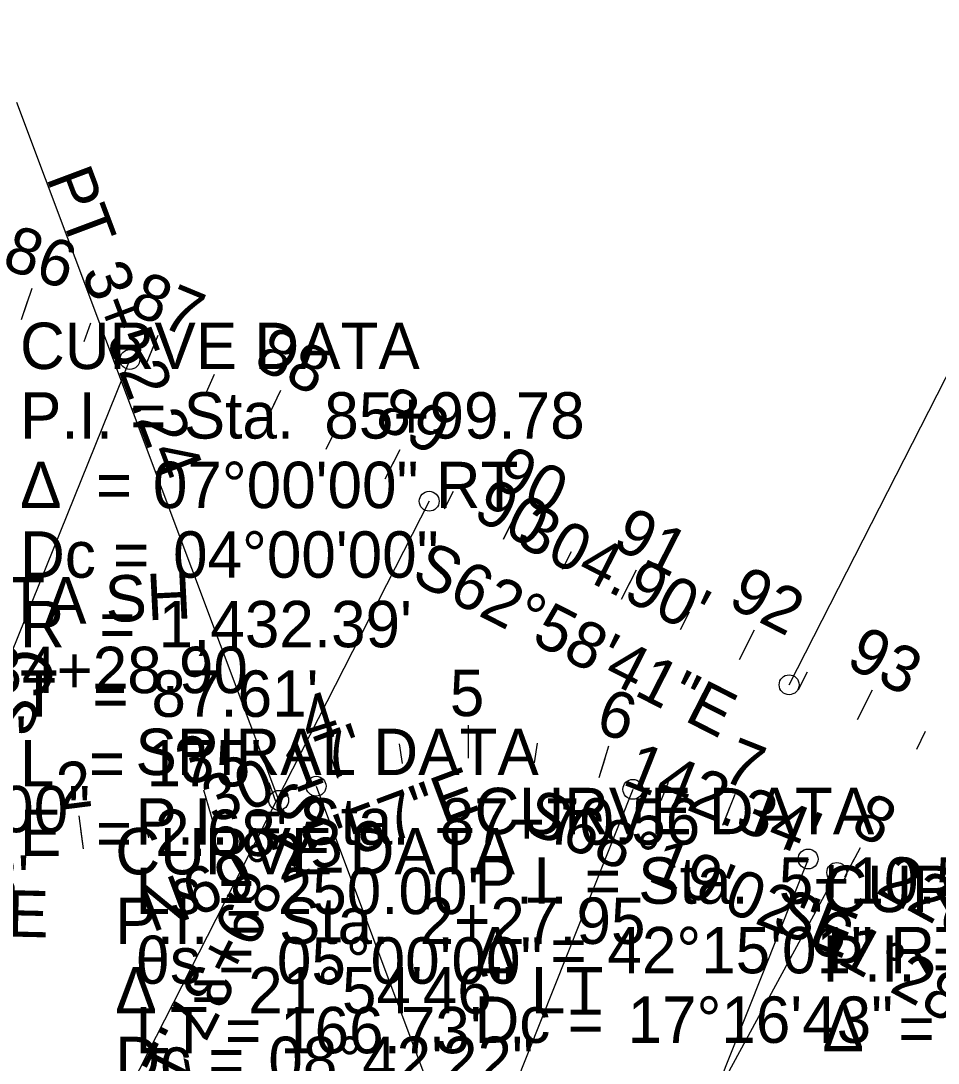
# Model space of a CAD drawing. Extents: x 2000474 to 2003418, y 251807 to 253801.
# Drawn here: x 2001296 to 2001988, y 252692 to 253479 of the extents above; entities that cross this region are included whole.
import ezdxf

# ---------------------------------------------------------------- set-up
doc = ezdxf.new("R2010")
doc.units = 0
for name, color, linetype in [('BD_X_Building', 7, 'Continuous'), ('DR_X_Flow_Arrow', 7, 'Continuous'), ('DV_X_Lot_Line', 7, 'Continuous'), ('DV_X_Property_Line', 7, 'Continuous'), ('DV_X_Township_Line', 7, 'Continuous'), ('GE_P_Alignment_100_Stations', 7, 'Continuous'), ('RW_P_Text', 7, 'Continuous'), ('RW_X_CL_100_Stations', 7, 'Continuous'), ('RW_X_CL_500_Stations', 7, 'Continuous'), ('SC_Scratch1', 7, 'Continuous'), ('SC_Scratch3', 7, 'Continuous'), ('SC_Scratch5', 7, 'Continuous'), ('SC_Shading1', 7, 'Continuous'), ('TX_X_50', 7, 'Continuous')]:
    doc.layers.add(name, color=color, linetype=linetype)

msp = doc.modelspace()

# ---------------------------------------------------------------- linework, layer by layer
at = {"layer": 'DR_X_Flow_Arrow'}
for p, q in [((2001490.69, 252890.46), (2001293.08, 253417.11)), ((2001633.98, 252922.2), (2001633.88, 252947.2)), ((2001535.56, 252906.8), (2001528.03, 252930.64)), ((2001584.19, 252918.22), (2001581.87, 252933.04)), ((2001683.81, 252918.65), (2001686, 252933.49)), ((2001732.54, 252907.66), (2001739.86, 252931.57)), ((2001488.59, 252889.68), (2001483.37, 252903.74)), ((2001779.38, 252890.21), (2001784.92, 252904.15)), ((2001441.1, 252874.07), (2001434.2, 252898.1)), ((2001518.94, 252901.06), (2001716.55, 252374.42)), ((2001757.95, 252898.74), (2001550.12, 252376.04)), ((2001825.84, 252871.74), (2001835.08, 252894.97)), ((2001343.26, 252853.87), (2001340.08, 252878.67)), ((2001392.56, 252862.11), (2001389.53, 252876.8)), ((2001872.3, 252853.27), (2001877.84, 252867.21)), ((2001917.84, 252832.75), (2001929.78, 252854.72)), ((2001890.21, 252846.15), (2001682.39, 252323.45)), ((2001911.83, 252836.02), (2001643.21, 252341.8)), ((2001961.77, 252808.88), (2001968.93, 252822.05))]:
    msp.add_line(p, q, dxfattribs=at)
for centre in [(2001518.94, 252901.06), (2001757.95, 252898.74), (2001490.69, 252890.46), (2001890.21, 252846.15), (2001911.83, 252836.02)]:
    msp.add_circle(centre, 7.5, dxfattribs=at)
at = {"layer": 'DV_X_Lot_Line'}
for p, q in [((2001633.98, 252922.2), (2001633.88, 252947.2)), ((2001535.56, 252906.8), (2001531.04, 252921.11)), ((2001732.54, 252907.66), (2001736.93, 252922)), ((2001441.1, 252874.07), (2001436.96, 252888.49)), ((2001825.84, 252871.74), (2001831.38, 252885.68)), ((2001343.26, 252853.87), (2001341.35, 252868.75)), ((2001917.84, 252832.75), (2001925, 252845.93))]:
    msp.add_line(p, q, dxfattribs=at)
at = {"layer": 'DV_X_Property_Line'}
for p, q in [((2001296.64, 253253.38), (2001301.41, 253267.6)), ((2001390.27, 253218.31), (2001396.01, 253232.17)), ((2001481.5, 253177.4), (2001487.96, 253190.94)), ((2001571.11, 253133.02), (2001577.9, 253146.4)), ((2001660.21, 253087.61), (2001666.93, 253100.79)), ((2001749.29, 253042.17), (2001756.11, 253055.54)), ((2001838.37, 252996.74), (2001845.19, 253010.1)), ((2001927.5, 252951.39), (2001934.25, 252964.78))]:
    msp.add_line(p, q, dxfattribs=at)
at = {"layer": 'RW_P_Text'}
for p, q in [((2001490.69, 252890.46), (2001293.08, 253417.11)), ((2001633.98, 252922.2), (2001633.92, 252937.2)), ((2001518.94, 252901.06), (2001716.55, 252374.42)), ((2001757.95, 252898.74), (2001550.12, 252376.04)), ((2001890.21, 252846.15), (2001682.39, 252323.45)), ((2001911.83, 252836.02), (2001643.21, 252341.8))]:
    msp.add_line(p, q, dxfattribs=at)
for centre in [(2001518.94, 252901.06), (2001757.95, 252898.74), (2001490.69, 252890.46), (2001890.21, 252846.15), (2001911.83, 252836.02)]:
    msp.add_circle(centre, 7.5, dxfattribs=at)
at = {"layer": 'RW_X_CL_100_Stations'}
for p, q in [((2001875.85, 252977.63), (2002131.41, 253478.72)), ((2001490.69, 252890.46), (2001293.08, 253417.11)), ((2001378.39, 253223.18), (2001167.48, 252701.72)), ((2001604.23, 253116.16), (2001348.67, 252615.06)), ((2001518.94, 252901.06), (2001716.55, 252374.42)), ((2001757.95, 252898.74), (2001550.12, 252376.04)), ((2001890.21, 252846.15), (2001682.39, 252323.45)), ((2001911.83, 252836.02), (2001643.21, 252341.8))]:
    msp.add_line(p, q, dxfattribs=at)
for centre in [(2001378.39, 253223.18), (2001604.23, 253116.16), (2001875.85, 252977.63), (2001518.94, 252901.06), (2001757.95, 252898.74), (2001490.69, 252890.46), (2001890.21, 252846.15), (2001911.83, 252836.02)]:
    msp.add_circle(centre, 7.5, dxfattribs=at)
at = {"layer": 'SC_Scratch3'}
for p, q in [((2001875.85, 252977.63), (2002131.41, 253478.72)), ((2001378.39, 253223.18), (2001167.48, 252701.72)), ((2001604.23, 253116.16), (2001348.67, 252615.06)), ((2001660.21, 253087.61), (2001671.57, 253109.88))]:
    msp.add_line(p, q, dxfattribs=at)
for centre in [(2001378.39, 253223.18), (2001604.23, 253116.16), (2001875.85, 252977.63)]:
    msp.add_circle(centre, 7.5, dxfattribs=at)
at = {"layer": 'TX_X_50'}
for p, q in [((2001875.85, 252977.63), (2002131.41, 253478.72)), ((2001296.64, 253253.38), (2001304.59, 253277.09)), ((2001343.76, 253236.66), (2001349.02, 253250.71)), ((2001390.27, 253218.31), (2001399.84, 253241.41)), ((2001378.39, 253223.18), (2001167.48, 252701.72)), ((2001436.15, 253198.45), (2001442.31, 253212.13)), ((2001481.5, 253177.4), (2001492.27, 253199.96)), ((2001526.44, 253155.48), (2001533.12, 253168.92)), ((2001571.11, 253133.02), (2001582.43, 253155.31)), ((2001615.67, 253110.32), (2001622.48, 253123.69)), ((2001604.23, 253116.16), (2001348.67, 252615.06)), ((2001660.21, 253087.61), (2001671.57, 253109.88)), ((2001704.75, 253064.89), (2001711.56, 253078.25)), ((2001749.29, 253042.17), (2001760.65, 253064.45)), ((2001793.83, 253019.46), (2001800.65, 253032.82)), ((2001838.37, 252996.74), (2001849.73, 253019.01)), ((2001882.92, 252974.03), (2001889.73, 252987.39)), ((2001927.5, 252951.39), (2001938.75, 252973.71)), ((2001972.26, 252929.11), (2001978.86, 252942.59))]:
    msp.add_line(p, q, dxfattribs=at)
for centre in [(2001378.39, 253223.18), (2001604.23, 253116.16), (2001875.85, 252977.63)]:
    msp.add_circle(centre, 7.5, dxfattribs=at)

# ---------------------------------------------------------------- texts
at = {"layer": 'BD_X_Building'}
for s, rotation, p in [("30.17'", 20.5675, (2001441.43, 252872.61)), ("142.34'", 338.31729, (2001748.96, 252902.94)), ('N69°25\'57"E', 20.5675, (2001395.04, 252790.49)), ('S68°19\'02"E', 338.31729, (2001673.29, 252867.83)), ("226.12'", 331.47468, (2001940.21, 252821.26)), ('S88°39\'17"E', 358.65462, (2001053.99, 252793.14)), ('S61°28\'29"E', 331.47468, (2001860.9, 252795.41))]:
    msp.add_text(s, height=35, rotation=rotation, dxfattribs=at).set_placement(p)
for s, p in [('CURVE DATA', (2001638.44, 252864.9)), ('CURVE DATA', (2001367.36, 252834.58)), ('P.I. = Sta. ', (2001638.44, 252812.4)), ('5+10.53', (2001868.05, 252812.4)), ('CURVE DATA', (2001901.02, 252806.08)), ('P.I. = Sta. ', (2001367.36, 252782.08)), ('2+27.95', (2001596.97, 252782.08)), ('Δ  = ', (2001638.44, 252759.9)), ('42°15\'01" RT', (2001738.72, 252759.9)), ('P.I. = Sta. ', (2001901.02, 252753.58)), ('Δ  = ', (2001367.36, 252729.58)), ('21°54\'46" LT', (2001467.64, 252729.58)), ('Dc = ', (2001638.44, 252707.4)), ('17°16\'43"', (2001753.93, 252707.4)), ('Δ  = ', (2001901.02, 252701.08)), ('Dc = ', (2001367.36, 252677.08)), ('08°42\'22"', (2001482.85, 252677.08))]:
    msp.add_text(s, height=35, dxfattribs=at).set_placement(p)
at = {"layer": 'DR_X_Flow_Arrow'}
for s, rotation, p in [('PT', 290.5675, (2001314.96, 253360.46)), ('3+52.24', 290.5675, (2001341.69, 253289.22)), ('5', 0.24994, (2001619.85, 252953.97)), ('4', 17.52864, (2001513.47, 252932.6)), ('6', 342.97124, (2001728.6, 252942.16)), ('3', 16.01907, (2001419.23, 252900.91)), ('7', 338.31729, (2001823.86, 252906.16)), ('2', 7.31304, (2001325.66, 252883.12)), ('8', 331.47468, (2001920.92, 252867.31))]:
    msp.add_text(s, height=35, rotation=rotation, dxfattribs=at).set_placement(p)
at = {"layer": 'DV_X_Lot_Line'}
msp.add_text('5', height=35, rotation=0.24994, dxfattribs=at).set_placement((2001619.85, 252953.97))
at = {"layer": 'DV_X_Property_Line'}
msp.add_text('90', height=35, rotation=332.97809, dxfattribs=at).set_placement((2001636.01, 253103.81))
at = {"layer": 'DV_X_Township_Line'}
for s, rotation, p in [("30.17'", 20.5675, (2001441.43, 252872.61)), ("142.34'", 338.31729, (2001748.96, 252902.94)), ('N69°25\'57"E', 20.5675, (2001395.04, 252790.49)), ('S68°19\'02"E', 338.31729, (2001673.29, 252867.83)), ("226.12'", 331.47468, (2001940.21, 252821.26)), ('S88°39\'17"E', 358.65462, (2001053.99, 252793.14)), ('S61°28\'29"E', 331.47468, (2001860.9, 252795.41))]:
    msp.add_text(s, height=35, rotation=rotation, dxfattribs=at).set_placement(p)
for s, p in [('CURVE DATA', (2001638.44, 252864.9)), ('CURVE DATA', (2001367.36, 252834.58)), ('P.I. = Sta. ', (2001638.44, 252812.4)), ('5+10.53', (2001868.05, 252812.4)), ('CURVE DATA', (2001901.02, 252806.08)), ('P.I. = Sta. ', (2001367.36, 252782.08)), ('2+27.95', (2001596.97, 252782.08)), ('Δ  = ', (2001638.44, 252759.9)), ('42°15\'01" RT', (2001738.72, 252759.9)), ('P.I. = Sta. ', (2001901.02, 252753.58)), ('Δ  = ', (2001367.36, 252729.58)), ('21°54\'46" LT', (2001467.64, 252729.58)), ('Dc = ', (2001638.44, 252707.4)), ('17°16\'43"', (2001753.93, 252707.4)), ('Δ  = ', (2001901.02, 252701.08)), ('Dc = ', (2001367.36, 252677.08)), ('08°42\'22"', (2001482.85, 252677.08))]:
    msp.add_text(s, height=35, dxfattribs=at).set_placement(p)
at = {"layer": 'GE_P_Alignment_100_Stations'}
for s, rotation, p in [("30.17'", 20.5675, (2001441.43, 252872.61)), ("142.34'", 338.31729, (2001748.96, 252902.94)), ('N69°25\'57"E', 20.5675, (2001395.04, 252790.49)), ('S68°19\'02"E', 338.31729, (2001673.29, 252867.83)), ("226.12'", 331.47468, (2001940.21, 252821.26)), ('S88°39\'17"E', 358.65462, (2001053.99, 252793.14)), ('S61°28\'29"E', 331.47468, (2001860.9, 252795.41))]:
    msp.add_text(s, height=35, rotation=rotation, dxfattribs=at).set_placement(p)
for s, p in [('CURVE DATA', (2001638.44, 252864.9)), ('CURVE DATA', (2001367.36, 252834.58)), ('P.I. = Sta. ', (2001638.44, 252812.4)), ('5+10.53', (2001868.05, 252812.4)), ('CURVE DATA', (2001901.02, 252806.08)), ('P.I. = Sta. ', (2001367.36, 252782.08)), ('2+27.95', (2001596.97, 252782.08)), ('Δ  = ', (2001638.44, 252759.9)), ('42°15\'01" RT', (2001738.72, 252759.9)), ('P.I. = Sta. ', (2001901.02, 252753.58)), ('Δ  = ', (2001367.36, 252729.58)), ('21°54\'46" LT', (2001467.64, 252729.58)), ('Dc = ', (2001638.44, 252707.4)), ('17°16\'43"', (2001753.93, 252707.4)), ('Δ  = ', (2001901.02, 252701.08)), ('Dc = ', (2001367.36, 252677.08)), ('08°42\'22"', (2001482.85, 252677.08))]:
    msp.add_text(s, height=35, dxfattribs=at).set_placement(p)
at = {"layer": 'RW_P_Text'}
for s, p in [('PT', (2001314.96, 253360.46)), ('3+52.24', (2001341.69, 253289.22))]:
    msp.add_text(s, height=35, rotation=290.5675, dxfattribs=at).set_placement(p)
at = {"layer": 'RW_X_CL_100_Stations'}
for s, rotation, p in [('PT', 290.5675, (2001314.96, 253360.46)), ('3+52.24', 290.5675, (2001341.69, 253289.22)), ("304.90'", 332.97809, (2001668.09, 253084.25)), ('S62°58\'41"E', 332.97809, (2001589.48, 253056.33)), ('CS', 247.97811, (2001292.45, 253009.12)), ('ST', 242.97809, (2001498.72, 252907.98)), ('89+37.17', 242.97809, (2001464.15, 252840.2))]:
    msp.add_text(s, height=35, rotation=rotation, dxfattribs=at).set_placement(p)
at = {"layer": 'RW_X_CL_500_Stations'}
for s, p in [('CURVE DATA', (2001295.48, 253215.96)), ('P.I. = Sta. ', (2001295.48, 253163.46)), ('85+99.78', (2001525.08, 253163.46)), ('Δ  = ', (2001295.48, 253110.96)), ('07°00\'00" RT', (2001395.75, 253110.96)), ('Dc = ', (2001295.48, 253058.46)), ('04°00\'00"', (2001410.96, 253058.46)), ('SPIRAL DATA', (2001041.33, 253023.87)), ('R  = ', (2001295.48, 253005.96)), ("1,432.39'", (2001400.08, 253005.96)), ('84+28.90', (2001270.94, 252971.37)), ('T  = ', (2001295.48, 252953.46)), ("87.61'", (2001394.63, 252953.46)), ("250.00'", (2001148.68, 252918.87)), ('SPIRAL DATA', (2001382.61, 252909.53)), ('L  = ', (2001295.48, 252900.96)), ("175'", (2001391.06, 252900.96)), ('05°00\'00"', (2001148.01, 252866.37)), ('P.I. = Sta. ', (2001382.61, 252857.03)), ('87+70.56', (2001612.22, 252857.03)), ('E  = ', (2001295.48, 252848.46)), ("2.68'", (2001397.38, 252848.46)), ("166.73'", (2001150.46, 252813.87)), ('Ls = ', (2001382.61, 252804.53)), ("250.00'", (2001489.96, 252804.53)), ('θs = ', (2001382.61, 252752.03)), ('05°00\'00"', (2001489.3, 252752.03)), ('LT = ', (2001382.61, 252699.53)), ("166.73'", (2001491.75, 252699.53))]:
    msp.add_text(s, height=35, dxfattribs=at).set_placement(p)
at = {"layer": 'SC_Scratch1'}
msp.add_text('SH', height=35, rotation=2.8513, dxfattribs=at).set_placement((2001360.59, 253024.64))
at = {"layer": 'SC_Scratch3'}
for s, rotation, p in [('90', 332.97809, (2001650.25, 253128.42)), ("304.90'", 332.97809, (2001668.09, 253084.25)), ('S62°58\'41"E', 332.97809, (2001589.48, 253056.33)), ('CS', 247.97811, (2001292.45, 253009.12)), ('ST', 242.97809, (2001498.72, 252907.98)), ('89+37.17', 242.97809, (2001464.15, 252840.2))]:
    msp.add_text(s, height=35, rotation=rotation, dxfattribs=at).set_placement(p)
at = {"layer": 'SC_Scratch5'}
for s, p in [('CURVE DATA', (2001295.48, 253215.96)), ('P.I. = Sta. ', (2001295.48, 253163.46)), ('85+99.78', (2001525.08, 253163.46)), ('Δ  = ', (2001295.48, 253110.96)), ('07°00\'00" RT', (2001395.75, 253110.96)), ('Dc = ', (2001295.48, 253058.46)), ('04°00\'00"', (2001410.96, 253058.46)), ('SPIRAL DATA', (2001041.33, 253023.87)), ('R  = ', (2001295.48, 253005.96)), ("1,432.39'", (2001400.08, 253005.96)), ('84+28.90', (2001270.94, 252971.37)), ('T  = ', (2001295.48, 252953.46)), ("87.61'", (2001394.63, 252953.46)), ("250.00'", (2001148.68, 252918.87)), ('SPIRAL DATA', (2001382.61, 252909.53)), ('L  = ', (2001295.48, 252900.96)), ("175'", (2001391.06, 252900.96)), ('05°00\'00"', (2001148.01, 252866.37)), ('P.I. = Sta. ', (2001382.61, 252857.03)), ('87+70.56', (2001612.22, 252857.03)), ('E  = ', (2001295.48, 252848.46)), ("2.68'", (2001397.38, 252848.46)), ("166.73'", (2001150.46, 252813.87)), ('Ls = ', (2001382.61, 252804.53)), ("250.00'", (2001489.96, 252804.53)), ('θs = ', (2001382.61, 252752.03)), ('05°00\'00"', (2001489.3, 252752.03)), ('LT = ', (2001382.61, 252699.53)), ("166.73'", (2001491.75, 252699.53))]:
    msp.add_text(s, height=35, dxfattribs=at).set_placement(p)
at = {"layer": 'SC_Shading1'}
for s, p in [('CURVE DATA', (2001295.48, 253215.96)), ('P.I. = Sta. ', (2001295.48, 253163.46)), ('85+99.78', (2001525.08, 253163.46)), ('Δ  = ', (2001295.48, 253110.96)), ('07°00\'00" RT', (2001395.75, 253110.96)), ('Dc = ', (2001295.48, 253058.46)), ('04°00\'00"', (2001410.96, 253058.46)), ('SPIRAL DATA', (2001041.33, 253023.87)), ('R  = ', (2001295.48, 253005.96)), ("1,432.39'", (2001400.08, 253005.96)), ('84+28.90', (2001270.94, 252971.37)), ('T  = ', (2001295.48, 252953.46)), ("87.61'", (2001394.63, 252953.46)), ("250.00'", (2001148.68, 252918.87)), ('SPIRAL DATA', (2001382.61, 252909.53)), ('L  = ', (2001295.48, 252900.96)), ("175'", (2001391.06, 252900.96)), ('05°00\'00"', (2001148.01, 252866.37)), ('P.I. = Sta. ', (2001382.61, 252857.03)), ('87+70.56', (2001612.22, 252857.03)), ('E  = ', (2001295.48, 252848.46)), ("2.68'", (2001397.38, 252848.46)), ("166.73'", (2001150.46, 252813.87)), ('Ls = ', (2001382.61, 252804.53)), ("250.00'", (2001489.96, 252804.53)), ('θs = ', (2001382.61, 252752.03)), ('05°00\'00"', (2001489.3, 252752.03)), ('LT = ', (2001382.61, 252699.53)), ("166.73'", (2001491.75, 252699.53))]:
    msp.add_text(s, height=35, dxfattribs=at).set_placement(p)
at = {"layer": 'TX_X_50'}
for s, rotation, p in [('86', 341.46477, (2001280.72, 253292.3)), ('87', 337.47794, (2001376.46, 253258.5)), ('88', 334.48327, (2001470.5, 253217.93)), ('89', 333.0886, (2001561.39, 253173.66)), ('90', 332.97809, (2001650.25, 253128.42)), ("304.90'", 332.97809, (2001668.09, 253084.25)), ('91', 332.97809, (2001741.21, 253082.03)), ('S62°58\'41"E', 332.97809, (2001589.48, 253056.33)), ('92', 332.97809, (2001828.49, 253037.52)), ('93', 333.2466, (2001917.53, 252992.07)), ('CS', 247.97811, (2001292.45, 253009.12)), ('ST', 242.97809, (2001498.72, 252907.98)), ('89+37.17', 242.97809, (2001464.15, 252840.2))]:
    msp.add_text(s, height=35, rotation=rotation, dxfattribs=at).set_placement(p)

doc.saveas('drawing.dxf')
